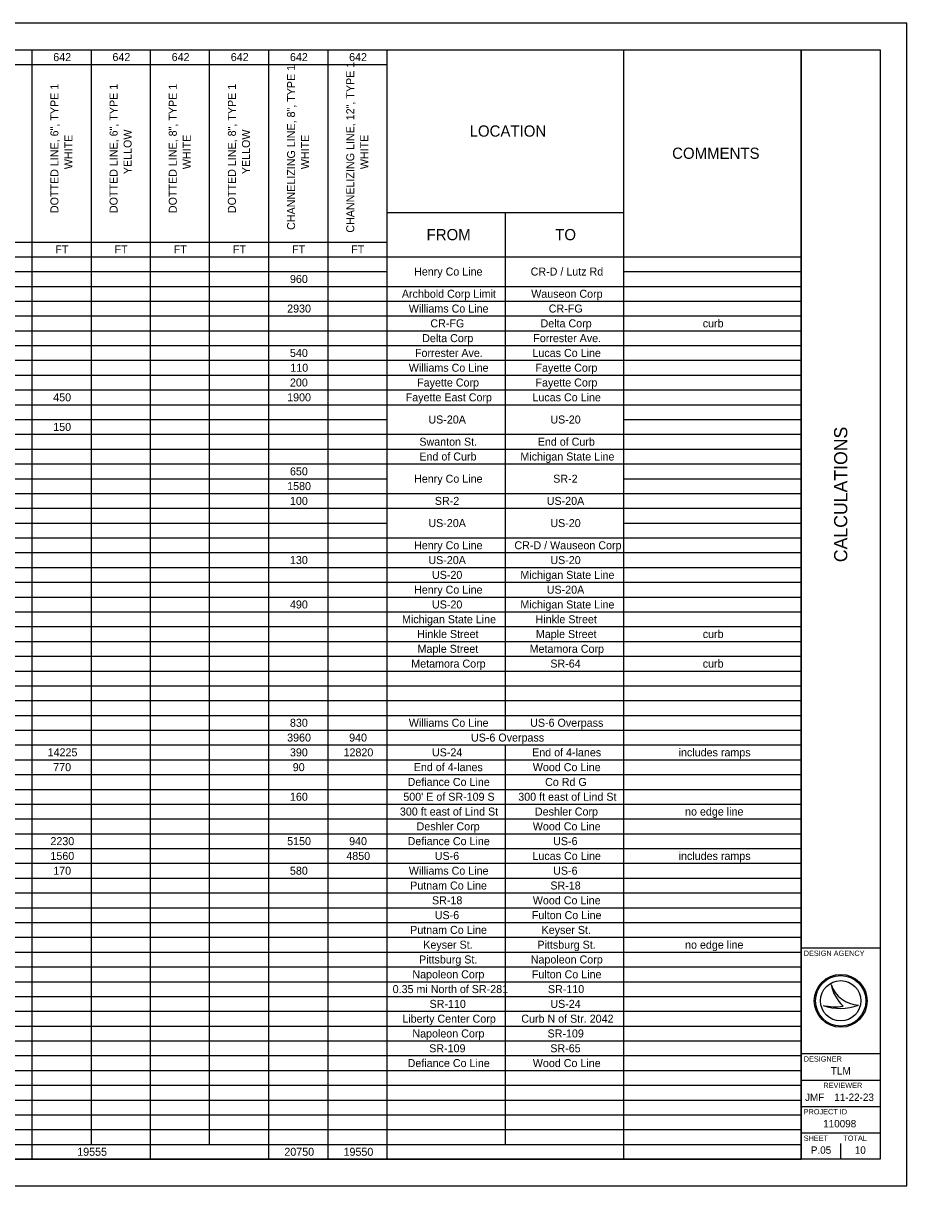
# Model space of a CAD drawing. Extents: x 0 to 34, y 0 to 22.
# Drawn here: x 17.28 to 34, y 0 to 22 of the extents above; entities that cross this region are included whole.
import ezdxf

# ---------------------------------------------------------------- set-up
doc = ezdxf.new("R2010")
doc.units = 0
for name, color, linetype in [('Default', 7, 'Continuous'), ('SH_Border', 7, 'Continuous'), ('SH_Cut_Line', 7, 'Continuous'), ('SH_Data', 7, 'Continuous')]:
    doc.layers.add(name, color=color, linetype=linetype)

msp = doc.modelspace()

# ---------------------------------------------------------------- linework, layer by layer
at = {"layer": 'Default'}
for p, q in [((1.5, 21.5), (32, 21.5)), ((17.442, 21.5), (17.442, 0.502)), ((18.562, 21.5), (18.562, 0.782)), ((19.681, 21.5), (19.681, 0.502)), ((20.801, 21.5), (20.801, 0.782)), ((21.921, 21.5), (21.921, 0.502)), ((23.041, 21.5), (23.041, 0.502)), ((24.161, 21.5), (24.161, 0.502)), ((28.64, 21.5), (28.64, 0.502)), ((32, 21.5), (32, 0.502)), ((8.483, 21.22), (24.161, 21.22)), ((24.161, 18.42), (28.64, 18.42)), ((26.401, 18.42), (26.401, 8.621)), ((8.483, 17.86), (24.161, 17.86)), ((1.5, 17.58), (32, 17.58)), ((2.505, 17.3), (24.161, 17.3)), ((28.64, 17.3), (32, 17.3)), ((2.505, 17.021), (32, 17.021)), ((2.505, 16.741), (32, 16.741)), ((2.505, 16.461), (32, 16.461)), ((2.505, 16.181), (32, 16.181)), ((2.505, 15.901), (32, 15.901)), ((2.505, 15.621), (32, 15.621)), ((2.505, 15.341), (32, 15.341)), ((2.505, 15.061), (32, 15.061)), ((2.505, 14.781), (32, 14.781)), ((2.505, 14.501), (24.161, 14.501)), ((28.64, 14.501), (32, 14.501)), ((2.505, 14.221), (32, 14.221)), ((2.505, 13.941), (32, 13.941)), ((2.505, 13.661), (32, 13.661)), ((2.505, 13.381), (24.161, 13.381)), ((28.64, 13.381), (32, 13.381)), ((2.505, 13.101), (32, 13.101)), ((2.505, 12.821), (32, 12.821)), ((2.505, 12.541), (24.161, 12.541)), ((28.64, 12.541), (32, 12.541)), ((2.505, 12.261), (32, 12.261)), ((2.505, 11.981), (32, 11.981)), ((2.505, 11.701), (32, 11.701)), ((2.505, 11.421), (32, 11.421)), ((2.505, 11.141), (32, 11.141)), ((2.505, 10.861), (32, 10.861)), ((2.505, 10.581), (32, 10.581)), ((2.505, 10.301), (32, 10.301)), ((2.505, 10.021), (32, 10.021)), ((2.505, 9.741), (32, 9.741)), ((1.5, 9.461), (32, 9.461)), ((1.5, 9.181), (32, 9.181)), ((1.5, 8.901), (32, 8.901)), ((2.505, 8.621), (32, 8.621)), ((2.505, 8.342), (32, 8.342)), ((26.401, 8.342), (26.401, 0.782)), ((2.505, 8.062), (32, 8.062)), ((2.505, 7.782), (32, 7.782)), ((2.505, 7.502), (32, 7.502)), ((2.505, 7.222), (32, 7.222)), ((2.505, 6.942), (32, 6.942)), ((2.505, 6.662), (32, 6.662)), ((2.505, 6.382), (32, 6.382)), ((2.505, 6.102), (32, 6.102)), ((2.505, 5.822), (32, 5.822)), ((2.505, 5.542), (32, 5.542)), ((2.505, 5.262), (32, 5.262)), ((2.505, 4.982), (32, 4.982)), ((2.505, 4.702), (32, 4.702)), ((2.505, 4.422), (32, 4.422)), ((2.505, 4.142), (32, 4.142)), ((2.505, 3.862), (32, 3.862)), ((2.505, 3.582), (32, 3.582)), ((2.505, 3.302), (32, 3.302)), ((2.505, 3.022), (32, 3.022)), ((2.505, 2.742), (32, 2.742)), ((2.505, 2.462), (32, 2.462)), ((2.505, 2.182), (32, 2.182)), ((2.505, 1.902), (32, 1.902)), ((1.5, 1.622), (32, 1.622)), ((1.5, 1.342), (32, 1.342)), ((1.5, 1.062), (32, 1.062)), ((1.5, 0.782), (32, 0.782)), ((1.5, 0.502), (32, 0.502))]:
    msp.add_line(p, q, dxfattribs=at)
at = {"layer": 'SH_Border'}
for p, q in [((32, 0.5), (32, 21.5)), ((32, 4.5), (33.5, 4.5)), ((32, 2.5), (33.5, 2.5)), ((32, 2), (33.5, 2)), ((32, 1.5), (33.5, 1.5)), ((32, 1), (33.5, 1))]:
    msp.add_line(p, q, dxfattribs=at)
msp.add_lwpolyline([(1.5, 21.5), (33.5, 21.5), (33.5, 0.5), (1.5, 0.5)], close=True, dxfattribs=at)
at = {"layer": 'SH_Cut_Line'}
msp.add_lwpolyline([(0, 0), (34, 0), (34, 22), (0, 22)], close=True, dxfattribs=at)
at = {"layer": 'SH_Data'}
for p, q in [((32.567, 3.81), (32.567, 3.81)), ((32.417, 3.41), (32.417, 3.41)), ((32.75, 3.5), (32.75, 3.5)), ((33.087, 3.419), (33.087, 3.419)), ((32.375, 0.675), (32.375, 0.675)), ((32.75, 0.5), (32.75, 0.8))]:
    msp.add_line(p, q, dxfattribs=at)
for radius in [0.5, 0.477, 0.477, 0.382]:
    msp.add_circle((32.75, 3.5), radius, dxfattribs=at)
for centre, radius, start, end in [((33.116, 3.998), 0.58, 198.9257, 198.9319), ((33.347, 3.97), 0.796, 191.6379, 191.6421), ((33.116, 3.998), 0.58, 198.9319, 267.1657), ((33.347, 3.97), 0.796, 191.6421, 226.0947), ((32.739, 4.37), 1.013, 251.4576, 290.0832), ((32.648, 4.654), 1.266, 259.4964, 259.4995), ((32.739, 4.37), 1.013, 251.4527, 251.4576), ((32.648, 4.654), 1.266, 259.4995, 276.6672)]:
    msp.add_arc(centre, radius, start, end, dxfattribs=at)

# ---------------------------------------------------------------- texts
at = {"layer": 'Default'}
for s, height, p in [('642', 0.1515, (17.848, 21.284)), ('642', 0.1515, (18.968, 21.284)), ('642', 0.1515, (20.088, 21.284)), ('642', 0.1515, (21.207, 21.284)), ('642', 0.1515, (22.327, 21.284)), ('642', 0.1515, (23.447, 21.284)), ('LOCATION', 0.2121, (25.727, 19.854)), ('COMMENTS', 0.2121, (29.56, 19.434)), ('FROM', 0.2121, (24.913, 17.894)), ('TO', 0.2121, (27.347, 17.894)), ('FT', 0.1515, (17.887, 17.645)), ('FT', 0.1515, (19.007, 17.645)), ('FT', 0.1515, (20.127, 17.645)), ('FT', 0.1515, (21.247, 17.645)), ('FT', 0.1515, (22.367, 17.645)), ('FT', 0.1515, (23.486, 17.645)), ('Henry Co Line', 0.15151, (24.676, 17.225)), ('CR-D / Lutz Rd', 0.15151, (26.882, 17.225)), ('960', 0.1515, (22.327, 17.085)), ('Archbold Corp Limit', 0.15151, (24.445, 16.805)), ('Wauseon Corp', 0.15151, (26.893, 16.805)), ('2930', 0.1515, (22.274, 16.525)), ('Williams Co Line', 0.15151, (24.576, 16.525)), ('CR-FG', 0.1515, (27.225, 16.525)), ('CR-FG', 0.1515, (24.985, 16.245)), ('Delta Corp', 0.1515, (27.069, 16.245)), ('curb', 0.1515, (30.139, 16.245)), ('Delta Corp', 0.1515, (24.829, 15.965)), ('Forrester Ave.', 0.15151, (26.932, 15.965)), ('Lucas Co Line', 0.15151, (26.916, 15.685)), ('540', 0.1515, (22.327, 15.685)), ('Forrester Ave.', 0.15151, (24.693, 15.685)), ('110', 0.1515, (22.334, 15.405)), ('Williams Co Line', 0.15151, (24.576, 15.405)), ('Fayette Corp', 0.15151, (26.974, 15.405)), ('200', 0.1515, (22.327, 15.125)), ('Fayette Corp', 0.15151, (24.734, 15.125)), ('Fayette Corp', 0.15151, (26.974, 15.125)), ('450', 0.1515, (17.847, 14.845)), ('1900', 0.1515, (22.274, 14.845)), ('Fayette East Corp', 0.15151, (24.517, 14.845)), ('Lucas Co Line', 0.15151, (26.916, 14.845)), ('US-20A', 0.1515, (24.947, 14.425)), ('US-20', 0.1515, (27.255, 14.425)), ('150', 0.1515, (17.847, 14.285)), ('Swanton St.', 0.15151, (24.776, 14.005)), ('End of Curb', 0.15151, (27.016, 14.005)), ('End of Curb', 0.15151, (24.776, 13.725)), ('Michigan State Line', 0.15151, (26.688, 13.725)), ('650', 0.1515, (22.327, 13.445)), ('Henry Co Line', 0.15151, (24.676, 13.305)), ('SR-2', 0.1515, (27.309, 13.305)), ('1580', 0.1515, (22.274, 13.165)), ('100', 0.1515, (22.327, 12.885)), ('SR-2', 0.1515, (25.069, 12.885)), ('US-20A', 0.1515, (27.187, 12.885)), ('US-20A', 0.1515, (24.947, 12.465)), ('US-20', 0.1515, (27.255, 12.465)), ('Henry Co Line', 0.15151, (24.676, 12.045)), ('CR-D / Wauseon Corp', 0.15151, (26.575, 12.045)), ('130', 0.1515, (22.327, 11.765)), ('US-20A', 0.1515, (24.947, 11.765)), ('US-20', 0.1515, (27.255, 11.765)), ('US-20', 0.1515, (25.015, 11.485)), ('Michigan State Line', 0.15151, (26.688, 11.485)), ('Henry Co Line', 0.15151, (24.676, 11.205)), ('US-20A', 0.1515, (27.187, 11.205)), ('490', 0.1515, (22.327, 10.925)), ('US-20', 0.1515, (25.015, 10.925)), ('Michigan State Line', 0.15151, (26.688, 10.925)), ('Michigan State Line', 0.15151, (24.448, 10.645)), ('Hinkle Street', 0.15151, (26.976, 10.645)), ('Hinkle Street', 0.15151, (24.736, 10.366)), ('Maple Street', 0.15151, (26.981, 10.366)), ('curb', 0.1515, (30.139, 10.366)), ('Maple Street', 0.15151, (24.742, 10.086)), ('Metamora Corp', 0.15151, (26.863, 10.086)), ('Metamora Corp', 0.15151, (24.623, 9.806)), ('SR-64', 0.1515, (27.255, 9.806)), ('curb', 0.1515, (30.139, 9.806)), ('830', 0.1515, (22.327, 8.686)), ('Williams Co Line', 0.15151, (24.576, 8.686)), ('US-6 Overpass', 0.15151, (26.873, 8.686)), ('3960', 0.1515, (22.274, 8.406)), ('940', 0.1515, (23.447, 8.406)), ('US-6 Overpass', 0.15151, (25.753, 8.406)), ('14225', 0.1515, (17.741, 8.126)), ('390', 0.1515, (22.327, 8.126)), ('12820', 0.1515, (23.341, 8.126)), ('US-24', 0.1515, (25.015, 8.126)), ('End of 4-lanes', 0.15151, (26.91, 8.126)), ('includes ramps', 0.15151, (29.683, 8.126)), ('770', 0.1515, (17.847, 7.846)), ('90', 0.1515, (22.38, 7.846)), ('End of 4-lanes', 0.15151, (24.67, 7.846)), ('Wood Co Line', 0.15151, (26.923, 7.846)), ('Defiance Co Line', 0.15151, (24.554, 7.566)), ('Co Rd G', 0.1515, (27.156, 7.566)), ('160', 0.1515, (22.327, 7.286)), ("500' E of SR-109 S", 0.15151, (24.473, 7.286)), ('300 ft east of Lind St', 0.15151, (26.648, 7.286)), ('300 ft east of Lind St', 0.15151, (24.408, 7.006)), ('Deshler Corp', 0.15151, (26.963, 7.006)), ('no edge line', 0.15151, (29.805, 7.006)), ('Deshler Corp', 0.15151, (24.724, 6.726)), ('Wood Co Line', 0.15151, (26.923, 6.726)), ('Defiance Co Line', 0.15151, (24.554, 6.446)), ('2230', 0.1515, (17.794, 6.446)), ('5150', 0.1515, (22.274, 6.446)), ('940', 0.1515, (23.447, 6.446)), ('US-6', 0.1515, (27.308, 6.446)), ('1560', 0.1515, (17.794, 6.166)), ('4850', 0.1515, (23.394, 6.166)), ('US-6', 0.1515, (25.068, 6.166)), ('Lucas Co Line', 0.15151, (26.916, 6.166)), ('includes ramps', 0.15151, (29.683, 6.166)), ('170', 0.1515, (17.847, 5.886)), ('580', 0.1515, (22.327, 5.886)), ('Williams Co Line', 0.15151, (24.576, 5.886)), ('US-6', 0.1515, (27.308, 5.886)), ('Putnam Co Line', 0.15151, (24.602, 5.606)), ('SR-18', 0.1515, (27.255, 5.606)), ('SR-18', 0.1515, (25.015, 5.326)), ('Wood Co Line', 0.15151, (26.923, 5.326)), ('US-6', 0.1515, (25.068, 5.046)), ('Fulton Co Line', 0.15151, (26.905, 5.046)), ('Putnam Co Line', 0.15151, (24.602, 4.766)), ('Keyser St.', 0.1515, (27.089, 4.766)), ('Keyser St.', 0.1515, (24.85, 4.486)), ('Pittsburg St.', 0.15151, (27.01, 4.486)), ('no edge line', 0.15151, (29.805, 4.486)), ('Pittsburg St.', 0.15151, (24.77, 4.206)), ('Napoleon Corp', 0.15151, (26.884, 4.206)), ('Napoleon Corp', 0.15151, (24.644, 3.926)), ('Fulton Co Line', 0.15151, (26.905, 3.926)), ('0.35 mi North of SR-281', 0.15151, (24.271, 3.646)), ('SR-110', 0.1515, (27.209, 3.646)), ('SR-110', 0.1515, (24.969, 3.366)), ('US-24', 0.1515, (27.255, 3.366)), ('Liberty Center Corp', 0.15151, (24.454, 3.086)), ('Curb N of Str. 2042', 0.15151, (26.705, 3.086)), ('Napoleon Corp', 0.15151, (24.644, 2.806)), ('SR-109', 0.1515, (27.202, 2.806)), ('SR-109', 0.1515, (24.962, 2.526)), ('SR-65', 0.1515, (27.254, 2.526)), ('Defiance Co Line', 0.15151, (24.554, 2.246)), ('Wood Co Line', 0.15151, (26.923, 2.246)), ('19555', 0.1515, (18.301, 0.567)), ('20750', 0.1515, (22.221, 0.567)), ('19550', 0.1515, (23.341, 0.567))]:
    msp.add_text(s, height=height, dxfattribs=at).set_placement(p)
for s, height, p in [('CHANNELIZING LINE, 8", TYPE 1', 0.15151, (22.424, 18.089)), ('CHANNELIZING LINE, 12", TYPE 1', 0.15151, (23.544, 18.036)), ('DOTTED LINE, 6", TYPE 1', 0.15151, (17.945, 18.407)), ('DOTTED LINE, 6", TYPE 1', 0.15151, (19.065, 18.407)), ('DOTTED LINE, 8", TYPE 1', 0.15151, (20.185, 18.407)), ('DOTTED LINE, 8", TYPE 1', 0.15151, (21.304, 18.407)), ('WHITE', 0.1515, (18.21, 19.238)), ('YELLOW', 0.1515, (19.33, 19.144)), ('WHITE', 0.1515, (20.45, 19.238)), ('YELLOW', 0.1515, (21.57, 19.144)), ('WHITE', 0.1515, (22.689, 19.238)), ('WHITE', 0.1515, (23.809, 19.238))]:
    msp.add_text(s, height=height, rotation=90, dxfattribs=at).set_placement(p)
at = {"layer": 'SH_Data'}
msp.add_text('CALCULATIONS', height=0.25, rotation=90, dxfattribs=at).set_placement((32.875, 11.801))
for s, height, p in [('DESIGN AGENCY', 0.1, (32.05, 4.35)), ('DESIGNER', 0.1, (32.05, 2.35)), ('TLM', 0.14, (32.565, 2.105)), ('REVIEWER', 0.1, (32.422, 1.85)), ('JMF', 0.14, (32.075, 1.605)), ('11-22-23', 0.14, (32.629, 1.605)), ('PROJECT ID', 0.1, (32.05, 1.35)), ('110098', 0.14, (32.419, 1.105)), ('SHEET', 0.1, (32.05, 0.85)), ('TOTAL', 0.1, (32.8, 0.85)), ('P.05', 0.14, (32.185, 0.605)), ('10', 0.14, (33.017, 0.605))]:
    msp.add_text(s, height=height, dxfattribs=at).set_placement(p)

doc.saveas('drawing.dxf')
